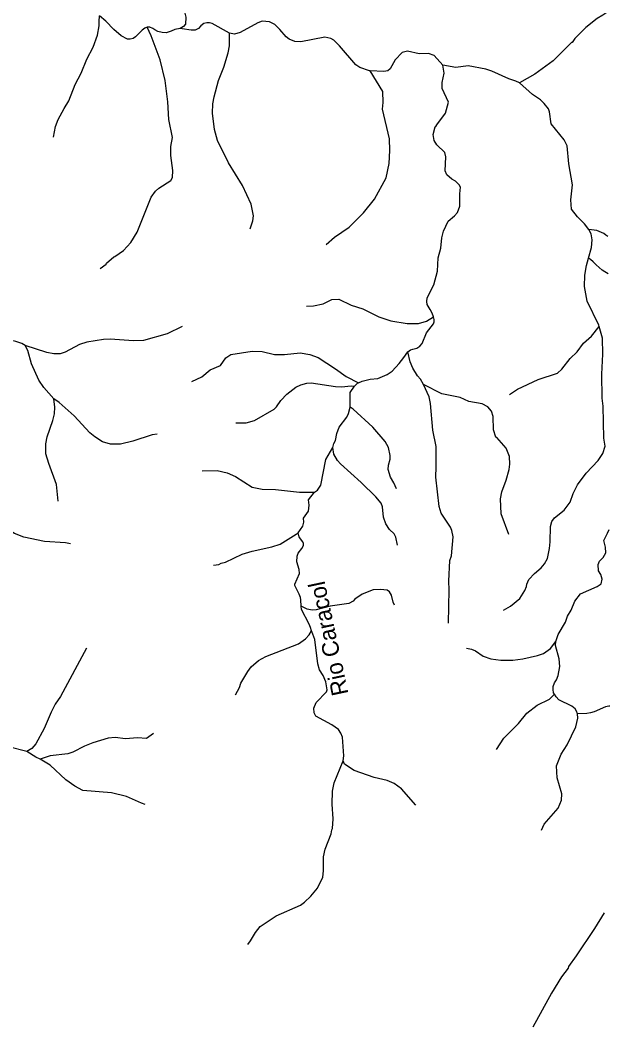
# Model space of a CAD drawing. Extents: x 280.4 to 335.6, y 8893.9 to 8949.5.
# Drawn here: x 329.87 to 335.55, y 8900.11 to 8909.74 of the extents above; entities that cross this region are included whole.
import ezdxf
from ezdxf.enums import TextEntityAlignment as Align

# ---------------------------------------------------------------- set-up
doc = ezdxf.new("R2010")
doc.units = 0
doc.header["$LTSCALE"] = 0.064
doc.linetypes.add('LONG_DASHED', pattern=[7.5, 6, -1.5])
doc.layers.add('61', color=7, linetype='Continuous')
doc.layers.add('7', color=7, linetype='Continuous', lineweight=25)
doc.layers.add('9', color=7, linetype='LONG_DASHED', lineweight=25)

msp = doc.modelspace()

# ---------------------------------------------------------------- linework, layer by layer
at = {"layer": '7'}
for points in [[(331.8902, 8910.9468), (331.8881, 8910.9446), (331.8667, 8910.9038), (331.8571, 8910.9021), (331.8406, 8910.866), (331.7831, 8910.785), (331.7158, 8910.7297), (331.6379, 8910.6343), (331.5575, 8910.4946), (331.5068, 8910.3711), (331.5004, 8910.244), (331.5098, 8910.149), (331.505, 8910.0858), (331.489, 8910.0374), (331.4141, 8909.9521), (331.4215, 8909.8955), (331.4516, 8909.8315), (331.4648, 8909.7675), (331.4617, 8909.7014), (331.4449, 8909.6778), (331.4111, 8909.6614)], [(330.1942, 8908.6152), (330.2113, 8908.716), (330.2391, 8908.7853), (330.2946, 8908.8907), (330.342, 8908.9624), (330.4001, 8909.1198), (330.4587, 8909.2295), (330.5152, 8909.366), (330.5734, 8909.4795), (330.6173, 8909.5956), (330.6335, 8909.6859), (330.6335, 8909.7267), (330.6371, 8909.7822)], [(331.0929, 8909.6734), (331.0704, 8909.6628), (331.0462, 8909.6426), (330.9819, 8909.5785), (330.958, 8909.563), (330.9311, 8909.558), (330.9048, 8909.5584), (330.8432, 8909.5895), (330.7732, 8909.6502), (330.698, 8909.7301), (330.6371, 8909.7822)], [(335.5179, 8909.8125), (335.4795, 8909.7893), (335.4243, 8909.7559), (335.314, 8909.6693), (335.2107, 8909.5632), (335.1854, 8909.5253), (335.1789, 8909.5255), (335.002, 8909.3496), (334.8251, 8909.2206), (334.6761, 8909.1363)], [(330.6421, 8907.3518), (330.6987, 8907.393), (330.7027, 8907.4026), (330.7729, 8907.464), (330.7847, 8907.4652), (330.8681, 8907.5247), (330.9368, 8907.6016), (330.9984, 8907.7003), (331.1325, 8908.0382), (331.1749, 8908.0953), (331.2072, 8908.1237), (331.3235, 8908.1981), (331.3371, 8908.2269), (331.3418, 8908.2952), (331.3212, 8908.4385), (331.3228, 8908.5248), (331.337, 8908.6119), (331.3037, 8908.7832), (331.2924, 8908.9559), (331.2665, 8909.1597), (331.2191, 8909.3589), (331.1337, 8909.5906), (331.0929, 8909.6734)], [(331.4111, 8909.6614), (331.3607, 8909.6495), (331.3237, 8909.633), (331.2764, 8909.6189), (331.2374, 8909.6203), (331.198, 8909.6306), (331.1694, 8909.6461), (331.1486, 8909.6614), (331.1194, 8909.6734), (331.0929, 8909.6734)], [(331.8873, 8909.6136), (331.7185, 8909.7095), (331.6949, 8909.7158), (331.6689, 8909.7147), (331.6405, 8909.7065), (331.6108, 8909.684), (331.589, 8909.6585), (331.5573, 8909.6446), (331.5172, 8909.6429), (331.431, 8909.6576), (331.4111, 8909.6614)], [(333.2406, 8909.2533), (333.2323, 8909.2537), (333.1408, 8909.2838), (333.1016, 8909.3115), (332.9444, 8909.494), (332.889, 8909.5462), (332.8628, 8909.5626), (332.8046, 8909.577), (332.5743, 8909.5309), (332.5167, 8909.5359), (332.4621, 8909.5562), (332.4308, 8909.5808), (332.3716, 8909.6511), (332.3221, 8909.697), (332.2716, 8909.7255), (332.2018, 8909.7303), (332.1598, 8909.7133), (331.9903, 8909.6207), (331.9337, 8909.6062), (331.8873, 8909.6136)], [(332.0868, 8907.7323), (332.1117, 8907.8085), (332.1176, 8907.8563), (332.0949, 8907.969), (332.0104, 8908.1505), (331.8779, 8908.3682), (331.7702, 8908.5819), (331.7408, 8908.6888), (331.7228, 8908.8447), (331.7259, 8908.9335), (331.7387, 8909.0021), (331.7822, 8909.1596), (331.8326, 8909.2887), (331.8743, 8909.4262), (331.8873, 8909.4947), (331.8873, 8909.6136)], [(333.9378, 8909.3072), (333.8556, 8909.3995), (333.8, 8909.4203), (333.7121, 8909.4175), (333.5978, 8909.4411), (333.5485, 8909.428), (333.4818, 8909.3596), (333.4327, 8909.2724), (333.4091, 8909.2527), (333.373, 8909.2462), (333.2406, 8909.2533)], [(334.0528, 8907.858), (334.081, 8907.891), (334.104, 8907.9507), (334.104, 8908.0699), (334.11, 8908.132), (334.0974, 8908.1555), (334.0623, 8908.1905), (334.0257, 8908.2112), (333.9792, 8908.2527), (333.9632, 8908.2911), (333.9678, 8908.4257), (333.9584, 8908.4683), (333.8823, 8908.5416), (333.8554, 8908.5811), (333.845, 8908.6393), (333.8661, 8908.7147), (333.8732, 8908.7171), (333.8804, 8908.7343), (333.9665, 8908.844), (333.9947, 8908.9496), (333.934, 8909.0842), (333.9315, 8909.1405), (333.9533, 8909.231), (333.9378, 8909.3072)], [(334.6761, 8909.1363), (334.6411, 8909.1545), (334.5756, 8909.1741), (334.4109, 8909.2493), (334.3533, 8909.2684), (334.1834, 8909.3017), (334.0639, 8909.2862), (333.9378, 8909.3072)], [(332.8167, 8907.5832), (332.8959, 8907.6512), (333.0367, 8907.7485), (333.1757, 8907.8863), (333.2822, 8908.0169), (333.3954, 8908.2243), (333.4224, 8908.3603), (333.4306, 8908.4872), (333.4255, 8908.5968), (333.3603, 8908.8831), (333.3651, 8908.9472), (333.3619, 8909.0551), (333.2406, 8909.2533)], [(335.3451, 8907.7268), (335.3032, 8907.7811), (335.2342, 8907.8464), (335.176, 8907.9229), (335.1707, 8908.0099), (335.1882, 8908.1563), (335.1517, 8908.357), (335.1371, 8908.5305), (335.1071, 8908.588), (334.9824, 8908.7442), (334.9653, 8908.8591), (334.9546, 8908.8862), (334.915, 8908.9385), (334.8796, 8908.9723), (334.8014, 8909.025), (334.6761, 8909.1363)], [(333.8487, 8906.8872), (333.8355, 8906.9208), (333.8159, 8906.956), (333.7899, 8907.0048), (333.7844, 8907.0333), (333.7886, 8907.0679), (333.8532, 8907.1947), (333.8865, 8907.3262), (333.896, 8907.4533), (333.921, 8907.5465), (333.9312, 8907.6452), (333.9462, 8907.7108), (333.9921, 8907.8051), (334.0528, 8907.858)], [(335.3416, 8907.4504), (335.3695, 8907.5536), (335.3766, 8907.6255), (335.3656, 8907.6836), (335.3451, 8907.7268)], [(335.5275, 8907.6585), (335.5093, 8907.6725), (335.4887, 8907.6883), (335.4217, 8907.7157), (335.3451, 8907.7268)], [(335.4442, 8906.7933), (335.4409, 8906.8051), (335.329, 8907.0376), (335.3034, 8907.1791), (335.3068, 8907.2854), (335.3226, 8907.3799), (335.3416, 8907.4504)], [(335.5292, 8907.299), (335.4975, 8907.32), (335.4738, 8907.3357), (335.4137, 8907.3847), (335.3866, 8907.4134), (335.3594, 8907.4358), (335.3416, 8907.4504)], [(332.6268, 8906.9893), (332.694, 8906.9913), (332.7893, 8907.012), (332.871, 8907.0518), (332.9379, 8907.0551), (333.0564, 8906.997), (333.1692, 8906.9627), (333.3251, 8906.8866), (333.4387, 8906.8473), (333.5953, 8906.8229), (333.704, 8906.8213), (333.7824, 8906.8449), (333.8487, 8906.8872)], [(329.9197, 8906.6108), (329.8897, 8906.6281), (329.8306, 8906.649), (329.6414, 8906.6906), (329.5613, 8906.7182), (329.4821, 8906.7657), (329.3467, 8906.8772), (329.2853, 8906.9111), (329.2286, 8906.9224), (329.0309, 8906.911)], [(333.604, 8906.549), (333.6268, 8906.567), (333.6503, 8906.5751), (333.6887, 8906.5853), (333.7195, 8906.6023), (333.7416, 8906.6298), (333.7809, 8906.7305), (333.8481, 8906.8192), (333.8546, 8906.8369), (333.8556, 8906.8601), (333.8487, 8906.8872)], [(331.4318, 8906.7939), (331.2866, 8906.7213), (331.0589, 8906.6586), (330.9637, 8906.6538), (330.7374, 8906.6697), (330.6734, 8906.6663), (330.5151, 8906.6409), (330.4441, 8906.6182), (330.3056, 8906.5473), (330.2577, 8906.5291), (330.1978, 8906.5292), (330.1274, 8906.5435), (329.9197, 8906.6108)], [(334.5246, 8904.0628), (334.5912, 8904.1006), (334.6789, 8904.1743), (334.7283, 8904.2514), (334.745, 8904.2906), (334.7468, 8904.3134), (334.7681, 8904.3576), (334.8209, 8904.4168), (334.8848, 8904.4712), (334.918, 8904.5078), (334.9453, 8904.5594), (334.9673, 8904.6579), (334.9737, 8904.7213), (334.974, 8904.8683), (334.9885, 8904.9171), (335.0148, 8904.953), (335.1066, 8905.0257), (335.1645, 8905.1032), (335.1921, 8905.1873), (335.235, 8905.2694), (335.3198, 8905.3825), (335.4333, 8905.5029), (335.4795, 8905.5718), (335.5012, 8905.6413), (335.4889, 8905.7197), (335.4824, 8906.0268), (335.4713, 8906.1037), (335.4697, 8906.3338), (335.4791, 8906.5251), (335.4759, 8906.6793), (335.4442, 8906.7933)], [(334.5797, 8906.1378), (334.6572, 8906.1883), (334.8562, 8906.2813), (335.0438, 8906.3447), (335.0834, 8906.3808), (335.1633, 8906.4864), (335.2329, 8906.5498), (335.2943, 8906.6334), (335.3704, 8906.7002), (335.4442, 8906.7933)], [(330.1968, 8906.0965), (330.0989, 8906.205), (330.053, 8906.2758), (329.9798, 8906.4324), (329.9457, 8906.5609), (329.9197, 8906.6108)], [(331.5256, 8906.262), (331.6192, 8906.3071), (331.7002, 8906.3753), (331.7986, 8906.4179), (331.8513, 8906.4912), (331.8987, 8906.5241), (332.1048, 8906.5545), (332.2014, 8906.5511), (332.3198, 8906.5227), (332.4165, 8906.5243), (332.5672, 8906.54), (332.6607, 8906.5243), (332.7385, 8906.4943), (332.9071, 8906.387), (333.0095, 8906.3119), (333.1264, 8906.2514)], [(333.1264, 8906.2514), (333.1646, 8906.2683), (333.2411, 8906.2853), (333.314, 8906.2913), (333.404, 8906.3295), (333.4508, 8906.364), (333.5201, 8906.4362), (333.564, 8906.4959), (333.604, 8906.549)], [(333.7546, 8906.2344), (333.7244, 8906.2854), (333.6941, 8906.3193), (333.6509, 8906.3927), (333.6238, 8906.4538), (333.604, 8906.549)], [(331.9482, 8905.8648), (332.0472, 8905.8654), (332.1261, 8905.8872), (332.3154, 8905.9961), (332.3395, 8906.02), (332.3802, 8906.0811), (332.4375, 8906.1403), (332.5239, 8906.2091), (332.5737, 8906.2327), (332.632, 8906.2489), (332.6718, 8906.2522), (332.9069, 8906.214), (332.9659, 8906.2108), (333.0572, 8906.2234), (333.0897, 8906.2201)], [(333.0484, 8906.015), (333.0492, 8906.1587), (333.0897, 8906.2201)], [(333.0897, 8906.2201), (333.1185, 8906.2479), (333.1264, 8906.2514)], [(333.993, 8903.9374), (334.0016, 8904.2591), (333.9969, 8904.3412), (334.0082, 8904.5415), (334.0239, 8904.5874), (334.0381, 8904.7683), (334.0272, 8904.8298), (334.0134, 8904.861), (333.9242, 8904.9953), (333.9038, 8905.0616), (333.8707, 8905.3416), (333.8768, 8905.4431), (333.8752, 8905.6366), (333.8419, 8905.7958), (333.8194, 8906.0508), (333.8082, 8906.1156), (333.7546, 8906.2344)], [(334.5736, 8904.7928), (334.5008, 8904.9899), (334.4942, 8905.1344), (334.5071, 8905.2031), (334.5489, 8905.315), (334.5771, 8905.416), (334.5836, 8905.4677), (334.5808, 8905.5412), (334.548, 8905.6212), (334.4589, 8905.7238), (334.4501, 8905.727), (334.4272, 8905.7982), (334.4253, 8905.9269), (334.4092, 8905.9787), (334.3725, 8906.0188), (334.3171, 8906.0497), (334.191, 8906.0715), (334.1064, 8906.1085), (333.9286, 8906.1449), (333.7546, 8906.2344)], [(330.2385, 8905.1136), (330.2225, 8905.2741), (330.1468, 8905.475), (330.1206, 8905.5678), (330.1186, 8905.6647), (330.1315, 8905.7301), (330.1871, 8905.8886), (330.2031, 8905.9525), (330.2049, 8906.0173), (330.1968, 8906.0965)], [(331.1893, 8905.7571), (331.1432, 8905.7517), (330.9567, 8905.6888), (330.8375, 8905.6591), (330.7399, 8905.6594), (330.6648, 8905.6833), (330.5908, 8905.7302), (330.5435, 8905.7698), (330.3915, 8905.9345), (330.2485, 8906.06), (330.1968, 8906.0965)], [(332.8798, 8905.6283), (332.8904, 8905.6657), (332.9075, 8905.6974), (332.9193, 8905.7629), (332.9429, 8905.8253), (333.0143, 8905.9207), (333.0325, 8905.9572), (333.0484, 8906.015)], [(333.492, 8905.2308), (333.4682, 8905.2874), (333.4356, 8905.3431), (333.4136, 8905.4168), (333.4166, 8905.4589), (333.4338, 8905.5157), (333.4339, 8905.5527), (333.4166, 8905.6288), (333.3857, 8905.6877), (333.2653, 8905.8226), (333.0781, 8905.9986), (333.0484, 8906.015)], [(332.7041, 8905.1982), (332.7339, 8905.219), (332.7652, 8905.2656), (332.8147, 8905.5143), (332.8798, 8905.6283)], [(333.5031, 8904.6878), (333.486, 8904.7658), (333.4715, 8904.7966), (333.4266, 8904.8397), (333.3915, 8904.8955), (333.3696, 8904.9596), (333.3604, 8905.0592), (333.3461, 8905.092), (333.2946, 8905.1552), (333.155, 8905.2917), (332.9534, 8905.4712), (332.9265, 8905.5029), (332.892, 8905.5655), (332.8798, 8905.6283)], [(331.624, 8905.4039), (331.7683, 8905.4063), (331.8656, 8905.3853), (331.9455, 8905.35), (332.1036, 8905.247), (332.2016, 8905.2273), (332.3287, 8905.2256), (332.5615, 8905.1985), (332.7041, 8905.1982)], [(332.5487, 8904.8088), (332.5909, 8904.8723), (332.6004, 8904.9106), (332.5992, 8904.948), (332.6453, 8905.0151), (332.6518, 8905.0725), (332.646, 8905.1261), (332.7041, 8905.1982)], [(330.357, 8904.701), (330.308, 8904.7102), (330.105, 8904.7251), (329.9068, 8904.7653), (329.8172, 8904.8021), (329.7809, 8904.8239), (329.7188, 8904.8834), (329.6255, 8905.0151), (329.5628, 8905.0876), (329.5645, 8905.0926), (329.5529, 8905.0957)], [(335.0257, 8903.7627), (335.0482, 8903.83), (335.1206, 8903.9472), (335.1404, 8904.0053), (335.1754, 8904.063), (335.2091, 8904.1493), (335.2655, 8904.2197), (335.4231, 8904.2923), (335.4635, 8904.3169), (335.474, 8904.3603), (335.4594, 8904.4061), (335.4372, 8904.4408), (335.4345, 8904.5013), (335.4474, 8904.5346), (335.4819, 8904.571), (335.5079, 8904.6155), (335.5035, 8904.669), (335.4875, 8904.7345), (335.5225, 8904.8035), (335.5403, 8904.8385)], [(331.7327, 8904.4963), (331.7831, 8904.5042), (331.8076, 8904.5169), (331.8475, 8904.5263), (332.0075, 8904.603), (332.1055, 8904.6307), (332.2933, 8904.6713), (332.3757, 8904.6987), (332.5276, 8904.796), (332.5487, 8904.8088)], [(332.5773, 8904.1015), (332.5736, 8904.1614), (332.5685, 8904.1844), (332.5559, 8904.2159), (332.5157, 8904.3009), (332.5149, 8904.3139), (332.5588, 8904.4158), (332.5557, 8904.4531), (332.5338, 8904.5282), (332.537, 8904.5819), (332.5487, 8904.6105), (332.5834, 8904.6568), (332.5974, 8904.6845), (332.5979, 8904.7045), (332.5912, 8904.7213), (332.569, 8904.7494), (332.5559, 8904.7682), (332.5487, 8904.8088)], [(333.4756, 8904.11), (333.4621, 8904.1399), (333.4464, 8904.2074), (333.4277, 8904.2398), (333.4052, 8904.2552), (333.3384, 8904.2629), (333.2683, 8904.2584), (333.1621, 8904.2166), (333.092, 8904.1682), (333.0779, 8904.1507), (333.0339, 8904.1288), (332.8546, 8904.1016), (332.7212, 8904.0651), (332.6812, 8904.063), (332.6341, 8904.0743), (332.5773, 8904.1015)], [(332.6746, 8903.865), (332.6665, 8903.8975), (332.6519, 8903.9282), (332.5805, 8904.071), (332.5773, 8904.1015)], [(331.9442, 8903.248), (331.983, 8903.3189), (331.9972, 8903.3596), (332.0629, 8903.4738), (332.0945, 8903.517), (332.1668, 8903.5791), (332.2371, 8903.6163), (332.5506, 8903.7405), (332.6193, 8903.789), (332.6529, 8903.8274), (332.6746, 8903.865)], [(332.9793, 8902.6125), (332.9854, 8902.6629), (332.973, 8902.8408), (332.9585, 8902.8814), (332.9354, 8902.9139), (332.8702, 8902.9598), (332.7167, 8903.0438), (332.6997, 8903.0754), (332.6968, 8903.1199), (332.7218, 8903.1741), (332.8201, 8903.2781), (332.8275, 8903.2962), (332.8134, 8903.3745), (332.7873, 8903.4334), (332.7526, 8903.4905), (332.7351, 8903.5472), (332.7072, 8903.7798), (332.6779, 8903.8591), (332.6746, 8903.865)], [(330.5115, 8903.6967), (330.2595, 8903.2321), (330.2085, 8903.16), (330.1691, 8903.0828), (330.103, 8902.9251), (330.0244, 8902.7778), (329.9838, 8902.7311), (329.9367, 8902.7037)], [(334.1676, 8903.6987), (334.2149, 8903.689), (334.2529, 8903.6733), (334.3268, 8903.622), (334.4014, 8903.5944), (334.4959, 8903.5816), (334.6124, 8903.5832), (334.708, 8903.5949), (334.8498, 8903.6281), (334.9082, 8903.6478), (334.975, 8903.6947), (335.0257, 8903.7627)], [(335.0128, 8903.2554), (335.004, 8903.2691), (335.0007, 8903.3013), (335.0023, 8903.3305), (335.0141, 8903.3633), (335.0319, 8903.3943), (335.0494, 8903.4344), (335.0647, 8903.5211), (335.0576, 8903.5961), (335.0238, 8903.723), (335.0257, 8903.7627)], [(334.455, 8902.7229), (334.5271, 8902.831), (334.6663, 8902.9734), (334.7492, 8903.0738), (334.8458, 8903.15), (334.9648, 8903.2061), (335.0128, 8903.2554)], [(335.235, 8903.0644), (335.2267, 8903.0924), (335.2134, 8903.113), (335.1807, 8903.1407), (335.0554, 8903.2021), (335.0296, 8903.228), (335.0128, 8903.2554)], [(335.5478, 8903.1402), (335.5354, 8903.1382), (335.5052, 8903.1333), (335.3941, 8903.0845), (335.3616, 8903.0749), (335.3258, 8903.0708), (335.235, 8903.0644)], [(334.8875, 8901.9453), (334.9148, 8902.0052), (335.0502, 8902.1593), (335.0819, 8902.2343), (335.0854, 8902.2962), (335.041, 8902.4516), (335.0316, 8902.566), (335.0789, 8902.677), (335.1366, 8902.7669), (335.2203, 8902.9409), (335.2392, 8903.0259), (335.235, 8903.0644)], [(331.1538, 8902.876), (331.0865, 8902.8298), (331.0024, 8902.8348), (330.8848, 8902.8269), (330.786, 8902.8396), (330.7205, 8902.8332), (330.5712, 8902.7883), (330.4918, 8902.7559), (330.3782, 8902.6974), (330.3301, 8902.6807), (330.1602, 8902.6634), (330.0641, 8902.631)], [(329.9367, 8902.7037), (329.7587, 8902.7486), (329.6643, 8902.7627), (329.3764, 8902.7819), (329.2736, 8902.7667)], [(330.0641, 8902.631), (330.023, 8902.6489), (329.9367, 8902.7037)], [(331.0756, 8902.1952), (331.0411, 8902.2055), (330.8964, 8902.2715), (330.7512, 8902.3053), (330.4746, 8902.3297), (330.3987, 8902.3702), (330.3131, 8902.4298), (330.16, 8902.5712), (330.0641, 8902.631)], [(332.0625, 8900.8479), (332.0893, 8900.8817), (332.1361, 8900.9615), (332.1827, 8901.0189), (332.3351, 8901.1235), (332.5694, 8901.2248), (332.6097, 8901.2527), (332.6706, 8901.3105), (332.7329, 8901.3885), (332.7844, 8901.4946), (332.7925, 8901.556), (332.7926, 8901.6896), (332.8074, 8901.7643), (332.866, 8901.912), (332.8711, 8901.9485), (332.8788, 8901.9614), (332.8851, 8902.0542), (332.8741, 8902.1976), (332.8763, 8902.3208), (332.8931, 8902.4022), (332.9793, 8902.6125)], [(333.6789, 8902.1871), (333.5403, 8902.3441), (333.4724, 8902.396), (333.4047, 8902.4249), (333.2777, 8902.4534), (333.0857, 8902.5203), (332.9943, 8902.5821), (332.9793, 8902.6125)]]:
    msp.add_lwpolyline(points, dxfattribs=at)
at = {"layer": '9'}
msp.add_lwpolyline([(335.4927, 8901.1509), (335.3997, 8901.0009), (335.2224, 8900.7375), (335.1485, 8900.6356), (335.1448, 8900.6196), (335.0822, 8900.535), (334.9835, 8900.3782), (334.8068, 8900.0502)], dxfattribs=at)

# ---------------------------------------------------------------- texts
at = {"layer": '61'}
msp.add_text('Rio Caracol', height=0.16, rotation=101.976, dxfattribs=at).set_placement((332.9163, 8903.806), align=Align.CENTER)

doc.saveas('drawing.dxf')
